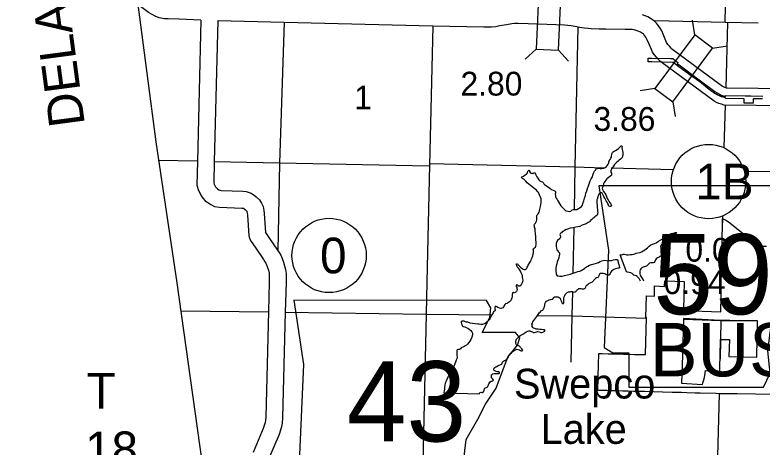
# Model space of a CAD drawing. Extents: x 77230 to 630905, y 790554 to 1662844.
# Drawn here: x 118792 to 145348, y 1541082 to 1556432 of the extents above; entities that cross this region are included whole.
import ezdxf

# ---------------------------------------------------------------- set-up
doc = ezdxf.new("R2010")
doc.units = 0
for name, color, linetype in [('Level 12', 7, 'Continuous'), ('Level 14', 7, 'Continuous'), ('Level 15', 7, 'Continuous'), ('Level 16', 7, 'Continuous'), ('Level 17', 7, 'Continuous'), ('Level 19', 7, 'Continuous'), ('Level 22', 7, 'Continuous'), ('Level 24', 7, 'Continuous'), ('Level 28', 7, 'Continuous'), ('Level 31', 7, 'Continuous'), ('Level 32', 7, 'Continuous'), ('Level 33', 7, 'Continuous')]:
    doc.layers.add(name, color=color, linetype=linetype)

msp = doc.modelspace()

# ---------------------------------------------------------------- linework, layer by layer
at = {"layer": 'Level 12'}
for points in [[(145367, 1553447), (145037, 1553454), (145034, 1553294), (144706, 1553297), (144709, 1553457), (144049, 1553465), (144049, 1553485), (143931, 1553519), (143906, 1553526), (143833, 1553558), (143778, 1553581), (143749, 1553598), (143637, 1553666), (143566, 1553718), (143408, 1553834), (143252, 1553957), (143095, 1554074), (142897, 1554222), (142744, 1554329), (142732, 1554337), (142647, 1554402), (142393, 1554592), (142180, 1554752), (142164, 1554746), (141426, 1554762), (141298, 1554765), (141302, 1554902), (141430, 1554899), (142092, 1554884), (142172, 1554882), (142354, 1554745), (142352, 1554730), (142336, 1554708), (142447, 1554625), (142733, 1554413), (142751, 1554400), (143671, 1553710), (143750, 1553665), (143896, 1553582), (144051, 1553537), (144052, 1553565), (144749, 1553558), (144947, 1553556), (145370, 1553551)], [(146000, 1542950), (145114, 1542961), (144466, 1542969), (144357, 1542971), (144198, 1542973), (143813, 1542978), (143716, 1542980), (143145, 1542996), (142965, 1543001), (142679, 1543009), (142480, 1543014), (142460, 1543015), (142152, 1543023), (141812, 1543033), (141486, 1543042), (141174, 1543050), (140835, 1543060), (140782, 1543061), (140588, 1543066), (140521, 1543068), (140492, 1543069), (140396, 1543072), (140204, 1543077), (140176, 1543078), (139953, 1543084), (139835, 1543087), (139511, 1543096), (139522, 1543546), (139524, 1543601), (139544, 1544407), (139642, 1544405), (139667, 1544404), (139880, 1544399), (140081, 1544394), (140100, 1544393), (140240, 1544390), (140300, 1544388), (140422, 1544385), (140536, 1544382), (140614, 1544380), (140815, 1544375), (141199, 1544366), (141237, 1545684), (141222, 1545684), (141240, 1546453), (141521, 1546443), (141528, 1546804), (141881, 1546784), (141897, 1546989), (142244, 1546974), (142577, 1546959), (142567, 1546445), (142557, 1545967), (142556, 1545928), (143880, 1545887), (143881, 1545920), (143889, 1546412), (143897, 1546888), (143897, 1546911), (143905, 1547305), (143910, 1547559), (143924, 1548247), (143944, 1549206), (144017, 1549171), (144044, 1549156), (144089, 1549130), (144160, 1549085), (144680, 1548670), (145239, 1548219), (145503, 1548213)]]:
    msp.add_lwpolyline(points, dxfattribs=at)
msp.add_lwpolyline([(143233, 1543306), (143248, 1543360), (143289, 1543509), (143318, 1543621), (143339, 1543806), (143452, 1543785), (143570, 1543734), (143662, 1543693), (143775, 1543636), (143834, 1543604), (143857, 1544298), (143865, 1544906), (144185, 1544902), (144168, 1544293), (144489, 1544288), (145165, 1544278), (145189, 1545571), (144201, 1545580), (143875, 1545582), (142551, 1545646), (142520, 1544332), (142490, 1543351)], close=True, dxfattribs=at)
at = {"layer": 'Level 14'}
for points in [[(123157, 1556800), (123802, 1551928), (124550, 1546914)], [(124550, 1546914), (125355, 1541164), (126178, 1535371), (126916, 1530075), (127152, 1528402), (127411, 1526569)]]:
    msp.add_lwpolyline(points, dxfattribs=at)
at = {"layer": 'Level 15'}
for points in [[(145207, 1556140), (144041, 1556163), (141540, 1556219)], [(133647, 1556032), (133523, 1551096), (133434, 1546946)], [(133434, 1546946), (133413, 1545803), (133290, 1540512), (133149, 1535230), (133009, 1528997)]]:
    msp.add_lwpolyline(points, dxfattribs=at)
at = {"layer": 'Level 16'}
for points in [[(144642, 1584845), (144619, 1582522), (144486, 1577238), (144365, 1571971), (144255, 1566690), (144126, 1561424), (144019, 1556165)], [(128360, 1556174), (128193, 1551161), (128141, 1548055)], [(138798, 1556005), (138694, 1551021), (138665, 1549515)], [(144123, 1556162), (144056, 1553844)], [(144038, 1553229), (143995, 1551726)], [(125268, 1551233), (123897, 1551266)], [(133513, 1551065), (128191, 1551161), (125874, 1551218)], [(139723, 1550993), (138684, 1551021), (133518, 1551141)], [(142183, 1550927), (139988, 1550986)], [(146603, 1550853), (144729, 1550871)], [(143940, 1549279), (143931, 1548782)], [(138653, 1548867), (138622, 1547260)], [(138609, 1546604), (138592, 1545740), (138552, 1544094)], [(124688, 1545920), (127803, 1545883)], [(128401, 1545875), (133411, 1545803), (135732, 1545776)], [(137360, 1545758), (138590, 1545744), (141237, 1545663)], [(142550, 1545623), (143884, 1545583), (145189, 1545564)], [(143888, 1545582), (143888, 1545579), (143854, 1544212)], [(143823, 1542978), (143757, 1540309), (143634, 1535036)]]:
    msp.add_lwpolyline(points, dxfattribs=at)
at = {"layer": 'Level 17'}
for points in [[(140023, 1551521), (140035, 1551551), (140060, 1551575), (140096, 1551594), (140142, 1551618), (140192, 1551648), (140248, 1551688), (140283, 1551720), (140313, 1551758), (140333, 1551778), (140353, 1551780), (140371, 1551764), (140375, 1551736), (140367, 1551706), (140371, 1551654), (140385, 1551599), (140398, 1551543), (140398, 1551499), (140394, 1551455), (140388, 1551419), (140372, 1551373), (140348, 1551342), (140315, 1551306), (140273, 1551278), (140233, 1551238), (140187, 1551198), (140144, 1551156), (140100, 1551116), (140070, 1551064), (140033, 1551012), (140009, 1550973), (139987, 1550929), (139975, 1550893), (139971, 1550851), (139991, 1550813), (139999, 1550781), (139998, 1550743), (139970, 1550711), (139922, 1550679), (139882, 1550651), (139835, 1550607), (139797, 1550565), (139763, 1550513), (139739, 1550477), (139717, 1550433), (139696, 1550371), (139684, 1550331), (139676, 1550297), (139660, 1550283), (139682, 1550235), (139716, 1550165), (139757, 1550097), (139789, 1550037), (139817, 1549977), (139847, 1549917), (139877, 1549859), (139917, 1549798), (139957, 1549732), (139981, 1549690), (139997, 1549656), (139976, 1549638), (139950, 1549630), (139928, 1549612), (139900, 1549666), (139870, 1549719), (139837, 1549783), (139811, 1549827), (139785, 1549875), (139755, 1549925), (139725, 1549983), (139703, 1550027), (139677, 1550073), (139665, 1550099), (139651, 1550115), (139623, 1550114), (139585, 1550096), (139549, 1550060), (139527, 1550022), (139524, 1549992), (139512, 1549970), (139504, 1549940), (139494, 1549908), (139480, 1549864), (139472, 1549814), (139477, 1549740), (139483, 1549666), (139485, 1549588), (139497, 1549526), (139501, 1549478), (139504, 1549452), (139508, 1549406), (139504, 1549374), (139498, 1549344), (139482, 1549320), (139444, 1549288), (139406, 1549258), (139363, 1549230), (139333, 1549202), (139295, 1549162), (139251, 1549126), (139220, 1549081)], [(136793, 1550659), (136815, 1550683), (136868, 1550707), (136928, 1550747), (136974, 1550781), (137010, 1550827), (137021, 1550871), (137031, 1550897), (137057, 1550917), (137077, 1550907), (137083, 1550866), (137109, 1550832), (137145, 1550814), (137173, 1550806), (137201, 1550804), (137233, 1550822), (137263, 1550826), (137287, 1550820), (137291, 1550778), (137315, 1550726), (137343, 1550684), (137377, 1550629), (137419, 1550573), (137453, 1550539), (137497, 1550515), (137541, 1550507), (137565, 1550479), (137595, 1550433), (137615, 1550405), (137647, 1550384), (137701, 1550350), (137755, 1550312), (137803, 1550274), (137861, 1550234), (137921, 1550205), (137969, 1550185), (137991, 1550173), (138009, 1550155), (138011, 1550127), (138005, 1550099), (137998, 1550063), (138000, 1550021), (138006, 1549979), (138032, 1549929), (138060, 1549873), (138088, 1549825), (138122, 1549767), (138162, 1549708), (138196, 1549652), (138237, 1549602), (138277, 1549566), (138311, 1549532), (138347, 1549500), (138389, 1549476), (138452, 1549457), (138502, 1549453), (138552, 1549463), (138588, 1549495), (138616, 1549509), (138646, 1549517), (138702, 1549518), (138767, 1549522), (138829, 1549554), (138885, 1549590), (138928, 1549628), (138960, 1549678), (138978, 1549732), (139012, 1549824), (139041, 1549927), (139069, 1550023), (139086, 1550095), (139114, 1550189), (139144, 1550271), (139175, 1550359), (139219, 1550467), (139238, 1550537), (139276, 1550615), (139316, 1550679), (139333, 1550739), (139361, 1550813), (139391, 1550877), (139425, 1550919), (139454, 1550962), (139486, 1550982), (139534, 1550988), (139592, 1550974), (139658, 1550974), (139718, 1550986), (139769, 1551013), (139817, 1551053), (139849, 1551091), (139877, 1551135), (139896, 1551179), (139904, 1551213), (139912, 1551251), (139944, 1551295), (139976, 1551347), (139993, 1551381), (140001, 1551425), (140013, 1551469), (140023, 1551521)], [(136840, 1546962), (136852, 1547014), (136845, 1547060), (136837, 1547110), (136827, 1547142), (136827, 1547174), (136815, 1547224), (136791, 1547270), (136757, 1547324), (136723, 1547384), (136688, 1547433), (136648, 1547483), (136632, 1547527), (136622, 1547559), (136614, 1547583), (136620, 1547591), (136644, 1547585), (136670, 1547573), (136684, 1547555), (136712, 1547529), (136732, 1547499), (136750, 1547478), (136778, 1547466), (136808, 1547442), (136830, 1547420), (136846, 1547404), (136876, 1547392), (136900, 1547390), (136928, 1547390), (136958, 1547410), (136982, 1547436), (136999, 1547472), (137023, 1547510), (137039, 1547547), (137057, 1547577), (137091, 1547633), (137112, 1547671), (137136, 1547717), (137158, 1547765), (137178, 1547819), (137197, 1547879), (137215, 1547931), (137225, 1547997), (137223, 1548045), (137221, 1548081), (137213, 1548115), (137226, 1548139), (137262, 1548163), (137290, 1548187), (137310, 1548219), (137316, 1548261), (137316, 1548303), (137313, 1548357), (137309, 1548443), (137305, 1548509), (137301, 1548571), (137299, 1548633), (137290, 1548693), (137288, 1548741), (137286, 1548797), (137278, 1548841), (137262, 1548887), (137254, 1548931), (137252, 1548957), (137263, 1548995), (137291, 1549031), (137311, 1549063), (137329, 1549109), (137345, 1549157), (137348, 1549211), (137344, 1549257), (137342, 1549293), (137354, 1549329), (137384, 1549365), (137423, 1549421), (137443, 1549471), (137453, 1549529), (137455, 1549577), (137469, 1549631), (137486, 1549695), (137498, 1549765), (137500, 1549831), (137494, 1549899), (137473, 1549957), (137449, 1550011), (137423, 1550069), (137399, 1550121), (137365, 1550165), (137333, 1550203), (137289, 1550242), (137235, 1550282), (137165, 1550332), (137115, 1550372), (137061, 1550416), (137001, 1550469), (136955, 1550523), (136921, 1550559), (136877, 1550601), (136837, 1550623), (136807, 1550641), (136793, 1550659)], [(139220, 1549081), (139170, 1549053), (139096, 1549017), (139024, 1548991), (138957, 1548963), (138875, 1548922), (138797, 1548910), (138724, 1548896), (138622, 1548873), (138532, 1548857), (138437, 1548825), (138367, 1548799), (138309, 1548766), (138246, 1548722), (138214, 1548696), (138184, 1548676), (138164, 1548632), (138170, 1548594), (138180, 1548550), (138182, 1548522), (138163, 1548498), (138133, 1548470), (138087, 1548440), (138049, 1548388), (138026, 1548330), (138024, 1548262), (138030, 1548206), (138038, 1548154), (138054, 1548092), (138082, 1548062), (138104, 1548032), (138126, 1548004), (138143, 1547978), (138153, 1547938), (138137, 1547874), (138121, 1547832), (138123, 1547796), (138105, 1547742), (138068, 1547664), (138052, 1547588), (138034, 1547524), (138019, 1547448), (138017, 1547396), (138021, 1547322), (138025, 1547264), (138035, 1547222), (138042, 1547200), (138070, 1547168), (138105, 1547160), (138159, 1547150), (138239, 1547151), (138323, 1547177), (138430, 1547197), (138526, 1547222), (138628, 1547260), (138735, 1547296), (138801, 1547313), (138865, 1547331), (138919, 1547349), (138974, 1547391), (139032, 1547429), (139076, 1547458), (139112, 1547484), (139155, 1547508), (139219, 1547542), (139291, 1547566), (139380, 1547592), (139458, 1547617), (139534, 1547635), (139596, 1547671), (139657, 1547695), (139701, 1547710), (139745, 1547716), (139813, 1547710), (139865, 1547702), (139930, 1547708), (140012, 1547707), (140072, 1547727), (140132, 1547743), (140206, 1547745), (140220, 1547703), (140234, 1547629), (140252, 1547563), (140272, 1547510), (140292, 1547462), (140280, 1547436), (140221, 1547441), (140139, 1547417), (140081, 1547391), (140039, 1547363), (139998, 1547331), (139966, 1547287), (139944, 1547247), (139920, 1547210), (139896, 1547192), (139866, 1547186), (139817, 1547196), (139781, 1547218), (139747, 1547232), (139703, 1547244), (139657, 1547252)], [(141022, 1546980), (141006, 1547024), (140974, 1547074), (140946, 1547110), (140912, 1547140), (140876, 1547162), (140840, 1547172), (140794, 1547191), (140762, 1547213), (140730, 1547243), (140680, 1547267), (140626, 1547279), (140568, 1547291), (140526, 1547307), (140307, 1547914), (140355, 1547910), (140384, 1547918), (140424, 1547928), (140456, 1547932), (140504, 1547924), (140546, 1547914), (140598, 1547913), (140654, 1547917), (140725, 1547925), (140777, 1547935), (140829, 1547951), (140877, 1547973), (140937, 1547980), (141012, 1547990), (141058, 1548014), (141124, 1548054), (141176, 1548090), (141231, 1548125), (141271, 1548161), (141339, 1548213), (141396, 1548267), (141452, 1548287), (141524, 1548308), (141588, 1548334), (141663, 1548390), (141753, 1548440), (141838, 1548489), (141924, 1548553), (141996, 1548595), (142059, 1548633), (142119, 1548663), (142175, 1548678), (142233, 1548694), (142270, 1548700), (142300, 1548700), (142310, 1548692), (142302, 1548678), (142271, 1548658), (142223, 1548656), (142179, 1548654), (142139, 1548620), (142085, 1548579), (142024, 1548529), (141966, 1548473), (141912, 1548417), (141855, 1548361), (141811, 1548313), (141787, 1548284), (141759, 1548252), (141742, 1548218), (141746, 1548130), (141754, 1548070), (141754, 1548028), (141759, 1547889), (141747, 1547868), (141687, 1547830), (141633, 1547800), (141588, 1547770), (141566, 1547734), (141538, 1547672), (141512, 1547636), (141476, 1547628), (141429, 1547625), (141381, 1547623), (141343, 1547615), (141323, 1547585), (141289, 1547551), (141238, 1547505), (141208, 1547493), (141162, 1547485), (141120, 1547472), (141076, 1547446), (141038, 1547416), (141015, 1547378), (141007, 1547326), (141001, 1547286), (141005, 1547234), (141019, 1547184), (141049, 1547132), (141071, 1547090), (141096, 1547059), (141116, 1547023), (141132, 1546987)], [(139657, 1547252), (139611, 1547251), (139567, 1547221), (139551, 1547181), (139532, 1547125), (139516, 1547103), (139466, 1547091), (139422, 1547069), (139388, 1547033), (139361, 1547001), (139341, 1546973)], [(136840, 1546962), (136810, 1546894), (136790, 1546846), (136772, 1546820), (136742, 1546800), (136706, 1546800), (136676, 1546818), (136654, 1546834), (136630, 1546843), (136610, 1546835), (136613, 1546795), (136627, 1546761), (136637, 1546713), (136641, 1546675), (136629, 1546629), (136616, 1546605), (136596, 1546583), (136578, 1546577), (136542, 1546565), (136516, 1546569), (136496, 1546568), (136482, 1546562), (136476, 1546540), (136466, 1546500), (136463, 1546444), (136451, 1546372), (136435, 1546336), (136414, 1546288), (136372, 1546244), (136336, 1546217), (136305, 1546191), (136271, 1546183), (136233, 1546169), (136203, 1546140), (136175, 1546088), (136153, 1546058), (136132, 1546024), (136102, 1546010), (136058, 1546008), (136016, 1546015), (135962, 1546041), (135916, 1546059), (135876, 1546081), (135862, 1546077), (135852, 1546046), (135852, 1545994), (135862, 1545960), (135857, 1545936), (135835, 1545906), (135807, 1545880), (135785, 1545854), (135763, 1545818), (135740, 1545778), (135716, 1545727), (135680, 1545659), (135645, 1545601), (135617, 1545569), (135585, 1545545), (135567, 1545532), (135538, 1545500), (135504, 1545472), (135468, 1545456), (135408, 1545440), (135352, 1545435), (135298, 1545443), (135242, 1545449), (135156, 1545458), (135060, 1545476), (134974, 1545487), (134894, 1545517), (134830, 1545520), (134756, 1545548), (134706, 1545552), (134676, 1545554), (134649, 1545535), (134653, 1545501), (134667, 1545459), (134681, 1545431), (134685, 1545403), (134697, 1545380), (134728, 1545366), (134780, 1545350), (134834, 1545328), (134888, 1545301), (134938, 1545271), (134994, 1545223), (135036, 1545175), (135054, 1545125), (135055, 1545071), (135027, 1544989), (134992, 1544905), (134960, 1544843), (134925, 1544792), (134883, 1544740), (134839, 1544698), (134799, 1544672), (134754, 1544649), (134710, 1544633), (134682, 1544621), (134658, 1544603), (134626, 1544565)], [(138336, 1546467), (138352, 1546505), (138380, 1546537), (138425, 1546567), (138473, 1546593), (138517, 1546598), (138555, 1546606), (138595, 1546602), (138635, 1546588), (138681, 1546591), (138703, 1546599), (138737, 1546623), (138756, 1546647), (138780, 1546667), (138810, 1546695), (138832, 1546712), (138876, 1546716), (138910, 1546710), (138944, 1546708), (138984, 1546700), (139012, 1546703), (139050, 1546713), (139067, 1546739), (139081, 1546767), (139099, 1546803), (139125, 1546829), (139165, 1546864), (139192, 1546896), (139238, 1546920), (139292, 1546934), (139320, 1546948), (139348, 1546973), (139341, 1546973)], [(136724, 1544530), (136756, 1544510), (136782, 1544501), (136812, 1544499), (136840, 1544513), (136837, 1544535), (136811, 1544573), (136777, 1544601), (136759, 1544621), (136749, 1544646), (136723, 1544666), (136689, 1544672), (136653, 1544690), (136625, 1544712), (136605, 1544734), (136595, 1544758), (136596, 1544802), (136600, 1544838), (136610, 1544880), (136622, 1544912), (136661, 1544948), (136727, 1545019), (136776, 1545057), (136844, 1545095), (136916, 1545142), (136966, 1545174), (137017, 1545204), (137057, 1545209), (137095, 1545207), (137137, 1545191), (137191, 1545169), (137215, 1545153), (137253, 1545146), (137299, 1545162), (137339, 1545178), (137383, 1545186), (137429, 1545177), (137461, 1545165), (137489, 1545153), (137519, 1545149), (137553, 1545161), (137583, 1545176), (137621, 1545196), (137630, 1545230), (137612, 1545248), (137562, 1545251), (137506, 1545257), (137452, 1545257), (137388, 1545268), (137316, 1545274), (137266, 1545292), (137228, 1545310), (137200, 1545333), (137174, 1545363), (137172, 1545409), (137170, 1545443), (137183, 1545477), (137201, 1545528), (137237, 1545582), (137270, 1545626), (137302, 1545676), (137342, 1545723), (137387, 1545793), (137431, 1545845), (137461, 1545879), (137494, 1545916), (137520, 1545928), (137558, 1545948), (137582, 1545988), (137602, 1546032), (137613, 1546080), (137623, 1546114), (137631, 1546174), (137653, 1546215), (137686, 1546259), (137730, 1546293), (137782, 1546315), (137826, 1546326), (137877, 1546336), (137899, 1546338), (137921, 1546358), (137945, 1546394), (137969, 1546417), (137999, 1546423), (138041, 1546423), (138103, 1546419), (138139, 1546389), (138169, 1546366), (138189, 1546328), (138207, 1546278), (138224, 1546244), (138234, 1546214), (138248, 1546188), (138276, 1546172), (138296, 1546176), (138304, 1546214), (138305, 1546302), (138299, 1546352), (138303, 1546390), (138320, 1546437), (138336, 1546467)], [(134626, 1544565), (134596, 1544550), (134553, 1544544), (134507, 1544534), (134493, 1544512), (134493, 1544438), (134498, 1544348), (134508, 1544278), (134497, 1544220), (134473, 1544165), (134451, 1544103), (134428, 1544043), (134388, 1543945), (134341, 1543854), (134305, 1543774), (134264, 1543698), (134220, 1543632), (134181, 1543561), (134149, 1543479), (134122, 1543419), (134088, 1543355), (134069, 1543283), (134061, 1543210), (134059, 1543142), (134052, 1543078), (134036, 1543006), (135299, 1542967), (135307, 1542993), (135324, 1543017), (135348, 1543027), (135384, 1543024), (135418, 1543024), (135436, 1543028), (135454, 1543062), (135468, 1543100), (135472, 1543124), (135481, 1543146), (135497, 1543176), (135521, 1543187), (135551, 1543197), (135575, 1543213), (135595, 1543235), (135617, 1543269), (135626, 1543297), (135636, 1543329), (135658, 1543369), (135682, 1543396), (135714, 1543420), (135741, 1543424), (135773, 1543438), (135797, 1543462), (135779, 1543494), (135755, 1543520), (135735, 1543546), (135729, 1543576), (135728, 1543608), (135736, 1543642), (135750, 1543662), (135784, 1543686), (135828, 1543693), (135878, 1543693), (135934, 1543693), (135978, 1543695), (136008, 1543696), (136021, 1543710), (136021, 1543740), (135987, 1543752), (135943, 1543755), (135895, 1543769), (135853, 1543787), (135823, 1543803), (135809, 1543823), (135811, 1543851), (135827, 1543883), (135851, 1543903), (135886, 1543931), (135924, 1543949), (135968, 1543982), (136002, 1543996), (136038, 1544008), (136058, 1544016), (136093, 1544028), (136105, 1544062), (136127, 1544101), (136163, 1544135), (136199, 1544153), (136234, 1544171), (136272, 1544199), (136298, 1544222), (136322, 1544262), (136340, 1544300), (136359, 1544340), (136395, 1544388), (136437, 1544429), (136462, 1544463), (136502, 1544493), (136544, 1544525), (136582, 1544541), (136624, 1544558), (136672, 1544546), (136724, 1544530)]]:
    msp.add_lwpolyline(points, dxfattribs=at)
at = {"layer": 'Level 19'}
for p, q in [((142956, 1555725), (142878, 1556247)), ((137322, 1555219), (136933, 1554862)), ((138113, 1555184), (138470, 1554795)), ((143592, 1555254), (144115, 1555332)), ((141542, 1553815), (141020, 1553737)), ((142179, 1553344), (142257, 1552822))]:
    msp.add_line(p, q, dxfattribs=at)
for points in [[(137425, 1557592), (137322, 1555219), (138113, 1555184), (138216, 1557558)], [(142179, 1553344), (143592, 1555254), (142956, 1555725), (141542, 1553815)]]:
    msp.add_lwpolyline(points, close=True, dxfattribs=at)
at = {"layer": 'Level 22'}
for points in [[(125405, 1556246), (124630, 1556278), (124234, 1556288), (124111, 1556299), (123915, 1556324), (123772, 1556383), (123539, 1556522), (123303, 1556694), (123151, 1556799)], [(147415, 1553794), (144106, 1553828), (144089, 1553834), (144021, 1553854), (143977, 1553873), (143945, 1553888), (142134, 1555229), (142114, 1555247), (142053, 1555317), (141999, 1555383), (141978, 1555414), (141956, 1555458), (141883, 1555626), (141780, 1555872), (141722, 1555964), (141671, 1556046), (141597, 1556134), (141525, 1556216), (141424, 1556282), (141291, 1556363), (141099, 1556439)], [(125398, 1556250), (125276, 1551227), (125257, 1550381), (125316, 1550198), (125370, 1550090), (125413, 1550011), (125473, 1549920), (125559, 1549832), (125643, 1549764), (125752, 1549696), (125889, 1549633), (126063, 1549601), (126859, 1549568), (126905, 1549566), (126915, 1549562), (126944, 1549541), (126983, 1549513), (127018, 1549478), (127029, 1549463), (127036, 1549445), (127047, 1549396), (127053, 1549324), (127109, 1548601), (127129, 1548495), (127191, 1548385), (127325, 1548184), (127625, 1547745), (127677, 1547664), (127710, 1547615), (127734, 1547557), (127770, 1547461), (127799, 1547360), (127824, 1547263), (127833, 1547208), (127832, 1547150), (127827, 1546940)], [(125998, 1556230), (125875, 1551214), (125859, 1550468), (125874, 1550424), (125901, 1550368), (125926, 1550323), (125942, 1550299), (125965, 1550275), (125993, 1550253), (126037, 1550225), (126071, 1550209), (126130, 1550199), (126890, 1550168), (127015, 1550160), (127193, 1550104), (127297, 1550026), (127370, 1549974), (127483, 1549863), (127561, 1549746), (127611, 1549624), (127641, 1549489), (127651, 1549374), (127703, 1548699), (127822, 1548520), (128126, 1548076), (128179, 1547993), (128243, 1547899), (128292, 1547777), (128340, 1547650), (128377, 1547519), (128413, 1547385), (128434, 1547248), (128432, 1547138), (128427, 1546927)], [(147409, 1553194), (144001, 1553229), (143905, 1553263), (143813, 1553290), (143733, 1553325), (143641, 1553366), (141754, 1554764), (141685, 1554825), (141594, 1554930), (141515, 1555027), (141459, 1555112), (141413, 1555203), (141332, 1555390), (141245, 1555596), (141214, 1555646), (141185, 1555692), (141142, 1555743), (141129, 1555757), (141103, 1555775), (141023, 1555824), (140903, 1555871), (140803, 1555901), (140735, 1555911), (140484, 1555910), (139794, 1555932), (139556, 1555930), (139275, 1555944), (139034, 1555963), (138874, 1555986), (138761, 1556005), (138567, 1556040), (138441, 1556054), (138321, 1556064), (137390, 1556104), (136683, 1556124), (136547, 1556123), (136458, 1556117), (136267, 1556084), (136022, 1556041), (135888, 1556014), (135734, 1556001), (135463, 1556001), (133646, 1556033), (128357, 1556165), (126003, 1556226)], [(127827, 1546941), (127802, 1545892), (127708, 1542150), (127698, 1542027), (127681, 1541957), (127614, 1541737), (127256, 1540885)], [(128427, 1546927), (128402, 1545878), (128307, 1542117), (128292, 1541933), (128261, 1541802), (128179, 1541533), (127809, 1540652)]]:
    msp.add_lwpolyline(points, dxfattribs=at)
at = {"layer": 'Level 24'}
for points in [[(139543, 1550362), (139885, 1548078), (139733, 1544614), (140038, 1544424), (140609, 1544424), (140609, 1543206), (145405, 1543206), (145633, 1543701), (145557, 1544500), (145671, 1545414), (146090, 1546137), (146357, 1546670), (146737, 1547241), (146966, 1547850), (147156, 1548345), (147499, 1548763), (147575, 1549030), (147422, 1549220), (146242, 1549220), (146509, 1549753), (146547, 1550096), (146389, 1550359)], [(128704, 1546295), (129046, 1544011), (128894, 1540547), (129199, 1540357), (129770, 1540357), (129770, 1539139), (134566, 1539139), (134794, 1539634), (134718, 1540433), (134832, 1541347), (135251, 1542070), (135517, 1542603), (135898, 1543174), (136127, 1543783), (136317, 1544278), (136659, 1544696), (136736, 1544963), (136583, 1545153), (135403, 1545153), (135670, 1545686), (135708, 1546029), (135550, 1546292)]]:
    msp.add_lwpolyline(points, close=True, dxfattribs=at)
at = {"layer": 'Level 33'}
for centre in [(143446, 1550513), (129959, 1547887)]:
    msp.add_circle(centre, 1320, dxfattribs=at)

# ---------------------------------------------------------------- texts
at = {"layer": 'Level 16'}
msp.add_text('1', height=845, dxfattribs=at).set_placement((130849, 1553079))
at = {"layer": 'Level 17'}
for s, p in [('Swepco', (136529, 1542806)), ('Lake', (137477, 1541195))]:
    msp.add_text(s, height=1056, dxfattribs=at).set_placement(p)
at = {"layer": 'Level 24'}
for s, height, p in [('59', 2851.2, (141485, 1545797)), ('BUS', 1900.8, (141356, 1543593)), ('43', 2851.2, (130589, 1541281))]:
    msp.add_text(s, height=height, dxfattribs=at).set_placement(p)
at = {"layer": 'Level 28'}
msp.add_text('DELAWARE', height=1267.2, rotation=97.5414, dxfattribs=at).set_placement((121282, 1552541))
for s, height, p in [('T', 1267, (121337, 1542450)), ('18', 1267.2, (121283, 1540367))]:
    msp.add_text(s, height=height, dxfattribs=at).set_placement(p)
at = {"layer": 'Level 31'}
for s, p in [('0.0', (142624, 1547668)), ('0.94', (141849, 1546515))]:
    msp.add_text(s, height=844.8, dxfattribs=at).set_placement(p)
at = {"layer": 'Level 32'}
for s, p in [('2.80', (134630, 1553568)), ('3.86', (139358, 1552314))]:
    msp.add_text(s, height=844.8, dxfattribs=at).set_placement(p)
at = {"layer": 'Level 33'}
for s, height, p in [('1B', 1267.2, (142974, 1549879)), ('0', 1267, (129636, 1547253))]:
    msp.add_text(s, height=height, dxfattribs=at).set_placement(p)

doc.saveas('drawing.dxf')
